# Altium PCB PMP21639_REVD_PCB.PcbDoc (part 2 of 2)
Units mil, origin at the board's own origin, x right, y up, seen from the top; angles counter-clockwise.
Board outline 3667.52 x 1155.04 mil, 4 copper layers (Top Layer, Signal Layer 1, Signal Layer 2, Bottom Layer), stack 90.224 mil thick; 122 components, 73 nets, 372 pads, 102 vias.
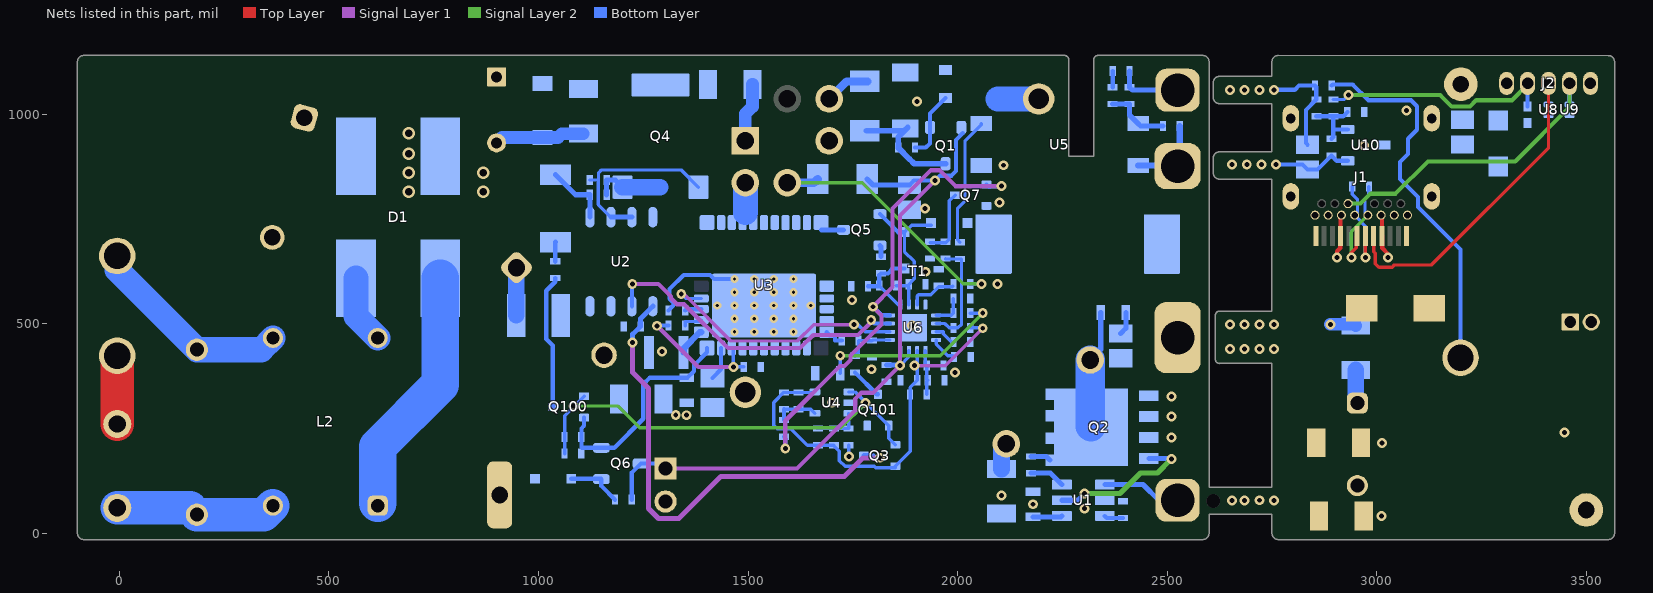
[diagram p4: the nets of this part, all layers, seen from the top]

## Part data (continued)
U10: library part CMP-0066199-1, "2.5V Low Iq Adjustable Precision Shunt Regulator, DBZ0003A (SOT-23-3)", Alternate Manufacturer="Texas Instruments"

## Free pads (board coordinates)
  rrect50% 105.31x102.36 hole 80: 0(2525,1057.09) 2(2525,78.74)
  rrect50% 110x110 hole 80: 1(2525,875.98)
  round 33 hole 33 unplated: 1(2610,76.69)
  rrect50% 60x160 hole 40 slot 120 at 90 deg: 2(907.38,91.54)
  rrect50% 110x170 hole 80 slot 140 at 90 deg: 2(2525,466.76)

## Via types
v1: diameter 23.62, hole 11.81, Top Layer to Bottom Layer, 72 vias
v2: diameter 19.68, hole 7.87, Top Layer to Bottom Layer, 22 vias
v3: diameter 30, hole 18, Top Layer to Bottom Layer, 6 vias
v4: diameter 23.62, hole 11.81, Top Layer to Bottom Layer, tented bottom, 2 vias

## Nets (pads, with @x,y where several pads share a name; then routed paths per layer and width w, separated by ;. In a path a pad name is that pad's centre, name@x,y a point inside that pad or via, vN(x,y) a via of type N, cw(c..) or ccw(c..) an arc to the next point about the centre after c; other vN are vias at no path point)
CC1: J1.A5 J2.3 U8.1 | length 806.9
  Top Layer w8: J1.A5@2992.64,709.29 2992.64,671.9 2996.64,667.9 2996.64,643.36 3005.33,634.67 3036.9,634.67 3042.23,640 3129.9,640 3410,920.1 J2.3@3410,1073.49
  Bottom Layer w8: U8.1@3410,1022.8 J2.3@3410,1073.49
CC2: J1.B5 J2.4 U9.1 | length 731
  Signal Layer 2 w10: J1.B5@2931.61,786.46 2961.09,786.46 2984.79,810.16 3045.16,810.16 3122.2,887.2 3330.46,887.2 3460,1016.75 J2.4@3460,1073.49
  Bottom Layer w12: U9.1@3460,1023.06 J2.4@3460,1073.49
CTL: J2.2 R42.1 R43.2 | length 559
  Signal Layer 2 w10: v1(2932.41,1045.91) 3151.39,1045.91 3178.85,1018.44 3222.66,1018.44 3237.27,1033.06 3322.67,1033.06 3360,1070.39 J2.2@3360,1073.49
  Bottom Layer w8: R42.1@2896.6,1034.79 2921.3,1034.79 v1(2932.41,1045.91)
  Bottom Layer w10: R43.2@3360,1018.53 J2.2@3360,1073.49
DN: J1.A7 J1.B7 R39.2 | length 248.4
  Top Layer w8: v1(2939.49,658.36) 2939.49,668.88 2951.36,680.75 2951.36,707.39 J1.A7@2953.27,709.29
  Signal Layer 2 w8: v1(2939.49,658.36) 2939.49,718.92 2978.86,758.29 J1.B7@2978.86,758.9
  Bottom Layer w8: J1.B7@2978.86,758.9 2971.91,765.85 2971.91,797.46 2981.36,806.91 R39.2@2981.36,827
DP: J1.A6 J1.B6 R39.1 | length 239
  Top Layer w8: v1(2972.95,658.09) J1.A6@2972.95,709.29
  Bottom Layer w8: R39.1@2941.36,827 2941.36,808.95 2954.31,796 2954.31,765.85 J1.B6@2947.36,758.9 2947.36,758.29 2972.95,732.7 v1(2972.95,658.09)
FB: C25.1 R21.1 R25.2 U6.10 | length 262.7
  Bottom Layer w8: U6.10@1948.78,500.32 1969.94,500.32 1980.25,490 C25.1@1990,490 2000.49,490 2009.37,498.89 2009.37,654.42 R21.1@2005.59,654.42 1972.04,654.42 R25.2@1971.14,655.32
HVG: C31.1 D7.2 D100.2 Q5.1 R11.2 U6.6 | length 365.3
  Bottom Layer w8: R11.2@1853.19,590.59 C31.1@1880.59,590.59 ; U6.6@1883.82,545.59 1883.82,587.36 C31.1@1880.59,590.59 ; D100.2@1937.01,735.16 1890.08,735.16 D7.2@1873.23,718.31 1873.23,672.11 1896.91,648.42 1896.91,606.91 C31.1@1880.59,590.59
  Bottom Layer w10: Q5.1@1814.53,761.33 1857.55,718.31 D7.2@1873.23,718.31
NetC1_1: C1.1 D1.1 L1.1
NetC2_1: C2.1 C3.1 C6.1 C7.1 D3.2 L1.2 T1.1 | length 472.2
  Bottom Layer w30: L1.2@900,931.26 912.9,944.16 D3.2@1010,944.16 1046.53,944.16 1055.87,953.51 C6.1@1107.24,953.51 ; T1.1@1493.59,936.3 1493.59,1001.03 1510.59,1018.03 C7.1@1510.59,1071.13
  Bottom Layer w40: C3.1@946.85,520 946.85,632.18 C2.1@948.02,633.35
NetC5_1: C5.1 R1.1 | length 54.9
  Bottom Layer w12: R1.1@2389.17,476.69 2401.54,489.06 C5.1@2401.54,526.5
NetC5_2: C5.2 Q2.5 Q2.6 Q2.7 Q2.8 Q2.9 R3.2 T1.7 | length 332.9
  Bottom Layer w12: R3.2@2175,183.19 2211.42,183.19 Q2.5@2220,174.6 ; T1.7@2316.42,413.47 2341.54,438.58 C5.2@2341.54,526.5
  Bottom Layer w70: T1.7@2316.42,413.47 2316.42,255.35 Q2.9@2318.43,253.34
NetC6_2: C6.2 C7.2 D3.1 Q4.2
NetC9_2: C9.2 D2.1 Q1.3 R2.1 | length 277.5
  Bottom Layer w13.78: D2.1@1782.69,960.16 C9.2@1872.88,960.16 ; C9.2@1881.08,968.36 C9.2@1872.88,960.16 ; Q1.3@1971.61,881.75 1896.47,881.75 1884.97,893.24 1884.6,893.24 1858.21,919.62 R2.1@1858.21,920 1858.21,945.49 C9.2@1872.88,960.16
NetC10_1: C10.1 L2.4 NEUT.1 | length 495.6
  Bottom Layer w60: NEUT.1@-5,661.66 -5,627.86 C10.1@185,437.86 338.53,437.86 L2.4@366.5,465.83
NetC10_2: C10.2 F1.1 L2.2 | length 387.2
  Bottom Layer w80: F1.1@-5,60.5 168.66,60.5 C10.2@185,44.16 344.83,44.16 L2.2@366.5,65.83
NetC11_1: C11.1 U1.4 | length 69.7
  Bottom Layer w12: C11.1@2180,39.2 2246.68,39.2 U1.4@2248.82,41.34
NetC13_1: C13.1 D6.1 U2.5 | length 155.3
  Bottom Layer w12: D6.1@1040.62,855.32 1088.34,807.6 C13.1@1122.68,807.6 1122.84,807.44 U2.5@1122.84,754.17
NetC15_1: C15.1 Q3.3 U2.1 | length 1180.1
  Signal Layer 1 w12: v1(1224.8,455) 1224.8,383.71 1262.7,345.81 1262.7,58.88 1286.4,35.18 1334.8,35.18 1435.12,135.5 1729.85,135.5 1774.36,180 v1(1814.53,180)
  Bottom Layer w12: v1(1224.8,455) 1224.8,474.79 C15.1@1243.8,493.78 1243.8,512.53 U2.1@1272.84,541.57 ; Q3.3@1776.63,185.44 1797.4,185.44 1802.84,180 v1(1814.53,180)
NetC16_2: C16.2 C17.1 C20.2 L3.1 R15.1 R22.2 R23.2 U3.12 U3.13 U3.14 U3.15 U3.16 U3.18 U3.19 U3.20 U3.21 U3.22 U3.23 U3.24 U3.33@1538.19,543.39 | length 284.8
  Bottom Layer w10: R15.1@1310,531.57 1322.5,544.07 1322.5,549.74 1312.77,559.47 1312.77,582.57 1346.51,616.31 1409.29,616.31 U3.33@1419.17,606.42 ; U3.33@1419.17,606.38 v2(1467.91,606.38) ; U3.16@1687.8,479.42 1694.61,472.6 1707.21,472.6 1707.21,460 R23.2@1723.66,460
  other v1: 1327.5,282.01 1352.97,281.61 1295,434.02
  other v2: 1467.91,480.4 1514.76,480.4 1561.61,480.4 1608.46,480.4 1467.91,511.9 1514.76,511.9 1561.61,511.9 1608.46,511.9 1426.57,543.39 1467.91,543.39 1514.76,543.39 1561.61,543.39 1608.46,543.39 1649.8,543.39 1467.91,574.89 1514.76,574.89 1561.61,574.89 1608.46,574.89 1514.76,606.38 1561.61,606.38 1608.46,606.38
NetC17_2: C17.2 R10.2 U3.25 | length 320.9
  Signal Layer 1 w10: v1(1283.15,495) 1381.15,397 v1(1465,397)
  Bottom Layer w8: U3.25@1461.42,442.01 1465,438.43 v1(1465,397) C17.2@1490,397
  Bottom Layer w10: v1(1283.15,495) 1283.5,495.35 R10.2@1310,495.35
NetC18_2: C18.2 R13.1 R17.1 U4.4 | length 104.1
  Bottom Layer w8: R13.1@1585.55,295.82 C18.2@1620,295.82 1649.65,295.82 U4.4@1659.65,285.82
  Bottom Layer w10: R17.1@1585.55,270 R13.1@1585.55,295.82
NetC20_1: C20.1 U3.26 | length 80.2
  Bottom Layer w10: C20.1@1415,370.43 1435.83,391.26 U3.26@1435.83,442.01
NetC21_1: C21.1 R16.2 | length 39
  Bottom Layer w10: C21.1@2370,1064.1 R16.2@2370,1103.1
NetC21_2: C21.2 R19.1 R24.2 U5.1 | length 157.1
  Bottom Layer w12: C21.2@2370,1024.1 2370.05,1024.04 R19.1@2410,1024.04 2410,998.03 U5.1@2430.54,977.49 2436.66,971.37 R24.2@2490,971.37
NetC24_2: C24.2 R18.1 R23.1 U6.1 | length 115.5
  Bottom Layer w8: R18.1@1755,423.61 1763.66,432.27 R23.1@1763.66,460 1763.98,459.68 C24.2@1795.86,459.68 1797.12,460.94 U6.1@1838.54,460.94
NetC26_1: C26.1 Q7.3 R25.1 | length 160.9
  Bottom Layer w8: C26.1@1934.21,693.81 1935.21,692.82 1971.46,692.82 1980.32,701.67 1980.32,792.93 Q7.3@1994.05,806.67
NetC29_1: C29.1 R32.2 R36.2 U6.13 | length 107.1
  Bottom Layer w8: U6.13@1923.19,435.35 1923.19,403.03 C29.1@1926.22,400 1926.22,367.4 R36.2@1928.62,365 1926.65,363.03 R32.2@1926.65,331.31
NetC38_1: C38.1 R41.1 R42.2 R45.1 U10.2 | length 169.8
  Bottom Layer w10: R41.1@2855.83,995 2896.39,995 R42.2@2896.6,994.79 ; C38.1@2891.99,941.12 2896.18,945.31 2896.18,960.98 ; R45.1@2930,1004.75 2920.04,994.79 R42.2@2896.6,994.79 ; U10.2@2930.92,963.48 2898.68,963.48 2896.18,960.98 ; 2896.18,960.98 2896.18,994.37 R42.2@2896.6,994.79
NetC100_2: C100.2 Q3.1 Q100.1 Q101.1 R100.1 U4.1 | length 1080.1
  Signal Layer 2 w8: v1(1083.15,303.49) 1189.77,303.49 1241.61,251.65 1721.56,251.65 v1(1780.29,310.38)
  Bottom Layer w8: R100.1@1062.31,190 C100.2@1062.31,230.01 1062.31,280.47 Q100.1@1108.93,327.08 ; U4.1@1740.35,337.01 1755.37,337.01 Q101.1@1835.59,256.78 1835.59,226.88 Q3.1@1851.44,211.03
NetC101_2: C101.2 R14.1 R20.2 U4.3 | length 109.3
  Bottom Layer w8: R14.1@1666.67,250 C101.2@1705,250 R20.2@1740,250 1740,285.47 U4.3@1740.35,285.82
NetC200_2: C200.2 R200.2 U6.9 | length 78.3
  Bottom Layer w8: U6.9@1948.78,520 1985,520 R200.2@1990,525 C200.2@1990,560
NetD1_2: D1.2 L2.3 | length 164.2
  Bottom Layer w60: D1.2@564.61,608.5 564.61,517.72 L2.3@616.5,465.83
NetD1_3: D1.3 L2.1 | length 598
  Bottom Layer w90: L2.1@616.5,72.13 616.5,206.22 765.39,355.12 D1.3@765.39,608.5
NetD2_2: D2.2 T1.9 | length 108.7
  Bottom Layer w19.68: T1.9@1693.59,1036.3 1735.39,1078.11 D2.2@1785,1078.11
NetD4_1: D4.1 Q1.1 R2.2 | length 163.9
  Bottom Layer w10: R2.2@1898.21,920 1924.06,920 1934.2,930.14 Q1.1@1934.2,968.36 1934.2,1001.57 D4.1@1971.14,1038.5
NetD6_2: D6.2 R4.2 | length 46.2
  Bottom Layer w11.81: R4.2@1040,648.79 1040,694.06 D6.2@1040.62,694.68
NetD8_1: D8.1 Q6.1 R9.1 | length 134.7
  Bottom Layer w10: D8.1@1078.31,130 1149.02,130 Q6.1@1150,129.02 1150,112.76 R9.1@1182.76,80
NetF1_2: F1.2 LINE.1 | length 163.1
  Top Layer w80: F1.2@-5,260.5 LINE.1@-5,423.61
NetL3_2: L3.2 U3.28 | length 67.9
  Bottom Layer w15: L3.2@1346.34,431.22 1346.34,440.88 1384.87,479.42 U3.28@1388.58,479.42
NetQ2_4: Q2.4 U1.5 | length 356.2
  Signal Layer 2 w12: v1(2302.76,94.95) 2387.74,94.95 2436.59,143.8 2476.86,143.8 v1(2510,176.93)
  Bottom Layer w12: U1.5@2248.82,78.74 2286.55,78.74 v1(2302.76,94.95) ; Q2.4@2456.22,178.34 2508.59,178.34 v1(2510,176.93)
NetQ4_1: Q4.1 R8.2 U2.6 U2.7 | length 446.7
  Bottom Layer w8: R8.2@1122.68,842.81 1142.68,842.81 ; U2.6@1172.84,754.17 1142.68,784.33 1142.68,836.5 1143.3,837.12 1143.3,859.73 1150.26,866.68 1340.64,866.68 Q4.1@1381.77,825.56
  Bottom Layer w12: U2.6@1172.84,754.17 U2.7@1222.84,754.17
NetQ5_2: Q5.2 R12.2 | length 27.5
  Bottom Layer w12: Q5.2@1814.53,686.53 1816.89,684.17 R12.2@1816.89,660
NetQ100_3: Q100.3 R4.1 | length 322.6
  Bottom Layer w10: Q100.3@1034.13,301.49 1034.13,447.98 1018.62,463.49 1018.62,578.62 1040,600 R4.1@1040,608.79
NetQ101_3: Q101.3 R18.2 | length 76.5
  Bottom Layer w10: R18.2@1755,383.61 1807.02,331.59 Q101.3@1810,331.59
NetR3_1: R3.1 U1.6 | length 85
  Bottom Layer w12: R3.1@2175,143.19 2221.77,143.19 U1.6@2248.82,116.14
NetR6_1: R6.1 U1.3 | length 45.6
  Bottom Layer w10: U1.3@2351.18,41.34 2355.9,36.62 R6.1@2394.8,36.62
NetR10_1: R10.1 U3.29 | length 49.9
  Bottom Layer w8: R10.1@1350,495.35 1350,505.07 1384.71,505.07 U3.29@1388.58,508.94
NetR15_2: R15.2 U3.30 | length 39.8
  Bottom Layer w10: R15.2@1350,531.57 1352.97,534.53 U3.30@1388.58,534.53
NetR21_2: R21.2 U5.4 | length 308.9
  Bottom Layer w8: R21.2@2005.59,694.42 1999.94,700.07 1999.94,775.84 2017.74,793.64 2017.74,936.2 2056.53,974.99 U5.4@2056.53,977.49
NetR26_2: R26.2 U6.11 | length 54.5
  Bottom Layer w8: U6.11@1948.78,480.63 1965.65,480.63 1965.65,476.24 1986.06,455.83 R26.2@1990.44,455.83
NetR28_1: R28.1 U6.12 | length 64.8
  Bottom Layer w8: U6.12@1948.78,460.94 1948.78,451.47 1976.38,423.87 1988.39,423.87 R28.1@1991.45,420.81
NetR37_2: R37.2 R38.2 U6.7 | length 115.3
  Bottom Layer w8: U6.7@1903.5,545.59 1903.5,566.19 1906.59,569.28 1936.01,569.28 1955,588.27 1987.65,588.27 R37.2@1988.64,589.25
NetR200_1: R200.1 RT1.2 | length 454
  Signal Layer 2 w8: v1(1720,423.61) 1720.08,423.68 1958.4,423.68 v1(2060,525.28)
  Bottom Layer w8: RT1.2@1720,381.85 v1(1720,423.61) ; R200.1@2030,525 2059.72,525 v1(2060,525.28)
OPTO_BOTTOM: C38.2 R101.2 U10.1 | length 194.7
  Bottom Layer w10: v1(2760,879.83) 2823.2,879.83 R101.2@2835,868.03 2858.9,868.03 C38.2@2891.99,901.12 2904.43,888.68 U10.1@2930.92,888.68
  other v1: 2655,879.52 2690,879.52 2725,879.52
OPTO_BOTTOM1: pad.1@2525,875.98 R24.1 U5.2 | length 192.5
  Bottom Layer w15: U5.2@2430.54,877.49 2523.49,877.49 pad.1@2525,875.98 2530,880.98 R24.1@2530,971.37
OPTO_TOP: R40.1 R41.2 R101.1 | length 256.2
  Bottom Layer w10: v1(2755,1057.93) 2804.54,1057.93 2814.77,1068.17 R40.1@2852.61,1068.17 2855.83,1064.95 R41.2@2855.83,1035 2830.95,1010.13 2830.95,931.13 R101.1@2835,927.08
  other v1: 2650,1057.62 2685,1057.62 2720,1057.62
OPTO_TOP1: pad.0 R16.1 R19.2 | length 156.9
  Bottom Layer w12: R16.1@2410,1103.1 R19.2@2410,1064.04 2416.95,1057.09 pad.0@2525,1057.09
PGND: C1.2 C2.2 C3.2 C9.1 C12.2 C14.1 C15.2 C19.2 C23.2 C24.1 C26.2 C27.2 C29.2 C30.2 C31.2 C200.1 D1.4 D4.2 D8.2 D100.1 pad.2@907.38,91.54 Q7.2 Q101.2 R20.1 R22.1 R26.1 R28.2 R36.1 R38.1 RT1.1 T1.8 T1.11 T1.12 U2.3 U2.4 U4.2 U5.3 U6.8 U6.16 U6.17@1893.66,490.47 | length 129.4
  Bottom Layer w8: R20.1@1740,210 1740,184.41 v1(1741.22,183.19)
  Bottom Layer w60: 2096.27,1036.3 T1.11@2193.59,1036.3 T1.11@2196.96,1032.93
  other v1: 1700,311.42 1993.56,383.61 1891.25,495.3 2095,595 1923.19,623.9 1922.56,775 2100,788.69 2109.42,878.06 1903.5,1030
  other v3: 690,815 868.15,815 690,860 868.2,859.73 690,905.4 690,954.44
  other v4: 1795,391.26 1748.46,556.09
PWMH: U2.2 U6.3 | length 768
  Signal Layer 1 w10: v1(1223.82,595) 1285.95,595 1315.96,564.99 1315.96,560.8 1330.42,546.33 1347.4,546.33 1451.93,441.81 1624.45,441.81 1655.55,472.91 1762.78,472.91 1793.9,504.03 v1(1793.9,508.39)
  Bottom Layer w10: U2.2@1222.84,541.57 1222.84,594.02 v1(1223.82,595) ; v1(1793.9,508.39) 1801.97,500.32 U6.3@1838.54,500.32
PWML: U3.31 U6.2 | length 620
  Signal Layer 1 w8: v1(1340.64,571.02) 1346.58,571.02 1458.92,458.68 1617.46,458.68 1656.38,497.6 v1(1752.56,497.6)
  Bottom Layer w8: v1(1340.64,571.02) 1351.54,560.12 U3.31@1388.58,560.12 ; v1(1752.56,497.6) 1762.35,497.6 1779.32,480.63 U6.2@1838.54,480.63
REF: C18.1 C25.2 C27.1 C101.1 Q3.2 R13.2 R14.2 R32.1 U4.5 U6.14 | length 1044
  Signal Layer 1 w8: v1(1897.6,400) 1970.94,400 v1(2060,489.06)
  Bottom Layer w8: U4.5@1659.65,337.01 1658.46,335.82 R13.2@1585.55,335.82 1561.68,311.95 1561.68,257.58 1569.88,249.37 1602.47,249.37 1641.84,210 R14.2@1666.67,210 C101.1@1705,210 1705,208.71 1717.54,196.17 1717.54,173.38 1731.41,159.5 1801.53,159.5 1804.72,156.32 1851.44,156.32 Q3.2@1851.44,159.85 1886.65,195.07 R32.1@1886.65,331.31 1886.65,347.83 C27.1@1903.82,365 1903.82,393.78 v1(1897.6,400) 1903.5,405.91 U6.14@1903.5,435.35 ; C25.2@2030,490 2059.06,490 v1(2060,489.06)
RUN: Q7.1 R17.2 U6.4 | length 1132.2
  Signal Layer 1 w10: v1(1588.87,202.05) 1588.87,268.46 1719.34,398.92 1730.22,398.92 1744.68,413.38 1744.68,424.27 1818.58,498.17 1818.58,519.91 v1(1798.06,540.44) 1844.84,587.23 1844.84,774.86 1936.28,866.3 1956.73,866.3 1994.92,828.11 v1(2105,828.11)
  Bottom Layer w10: R17.2@1585.55,230 1588.87,226.68 v1(1588.87,202.05) ; v1(1798.06,540.44) 1818.5,520 U6.4@1838.54,520 ; Q7.1@2068.85,832.26 2073,828.11 v1(2105,828.11)
S: C33.1 C34.1 L4.1 L5.1 | length 61.5
  Bottom Layer w30: v1(2889.75,498.46) 2947.09,498.46 L4.1@2950,495.55
  other v1: 2655,77.76 2685,77.76 2755,77.76 2720,78.74
S1: C8.1 pad.2@2525,78.74 T1.4 U1.1 | length 209
  Bottom Layer w12: U1.1@2351.18,116.14 2442.6,116.14 pad.2@2480,78.74
  Bottom Layer w40: C8.1@2105,153.54 2105,202.05 T1.4@2116.42,213.47
SGND: C32.2 C33.2 C34.2 C36.2 D9.2 J1.A1 J1.A12 J1.B1 J1.B12 J1.M1 J1.M2 J1.S1 J1.S2 J1.S3 J1.S4 J2.5 J3.2 R43.1 R45.2 TP3.1 U8.2 U9.2 U10.3
  other v1: 3011.76,41.34 3012.32,215.57 3448.15,240 2650,440 2685,440 2720,440 2755,440 2650,498.46 2685,498.46 2720,498.46 2755,498.46 2969.27,925 3071.43,1008.46
SGND1: C8.2 C11.2 C19.1 pad.2@2525,466.76 Q2.1 Q2.2 Q2.3 R1.2 R6.2 U1.2
  other v1: 2302.76,58.51 2180,69.2 2105,90 2510,228.42 2510,278.93 2510,326.61
SWS: C30.1 D7.1 R11.1 R12.1 U6.5 | length 189.1
  Bottom Layer w8: R11.1@1813.19,590.59 1858.19,545.59 U6.5@1864.13,545.59
  Bottom Layer w10: C30.1@1786.34,589.25 1811.85,589.25 R11.1@1813.19,590.59 1813.19,616.3 R12.1@1816.89,620 1833.64,620 1845.33,631.69 D7.1@1873.23,631.69
VBUS: C36.1 D9.1 J1.A4 J1.A9 J1.B4 J1.B9 J2.1 TP1.1 | length 212.6
  Top Layer w10: v1(2905.47,658.09) 2905.47,672.82 2912.99,680.34 2912.99,708.39 J1.A9@2913.9,709.29 2913.9,756.93 J1.B4@2915.87,758.9 ; J1.B9@3010.35,758.9 3012.32,756.93 J1.A4@3012.32,709.29 3013.23,708.39 3013.23,680.34 3027.09,666.48 v1(3027.09,658.36)
VCCL: C16.1 C100.1 Q6.2 Q100.2 R100.2 U3.27 | length 535.2
  Bottom Layer w10: Q100.2@1108.93,275.9 1108.93,256.62 1102.31,250 C100.1@1102.31,230.01 1102.31,205 1103.49,203.83 Q6.2@1150,203.83 1180.68,203.83 1250,273.15 1250,355.43 1265.72,371.16 C16.1@1353.5,371.16 1355.66,371.16 1371.02,386.52 1371.02,400.48 1402.36,431.82 U3.27@1402.36,442.01
VDD: C12.1 C14.2 C23.1 D5.1 Q1.2 Q6.3 R9.2 U6.15 | length 1718.7
  Signal Layer 1 w10: C12.1@1303.15,154.37 1617.09,154.37 1755.6,292.88 1755.6,320.6 1770.06,335.06 1797.78,335.06 v1(1862.72,400) 1862.72,757.82 v1(1946.51,841.61)
  Bottom Layer w8: v1(1862.72,400) 1883.82,421.1 U6.15@1883.82,435.35
  Bottom Layer w10: R9.2@1222.76,80 1222.76,144.69 Q6.3@1244.49,166.42 1291.1,166.42 C12.1@1303.15,154.37 ; C14.2@1885,831 1895.61,841.61 v1(1946.51,841.61) 1958.02,853.12 1985.29,853.12 1996.29,864.12 1996.29,938.62 Q1.2@2012.1,954.42
  Bottom Layer w12: D5.1@1784.06,845 1798.06,831 C14.2@1885,831 ; C23.1@1830.29,401.46 1861.25,401.46 v1(1862.72,400)
VO: C32.1 J3.1 L4.2 L5.2 R40.2 TP2.1 | length 982.9
  Bottom Layer w10: R40.2@2892.61,1068.17 2895.03,1070.59 2942.64,1070.59 2980.08,1033.15 3081.66,1033.15 3096.12,1018.69 3096.12,962.77 3074.68,941.34 3074.68,905.18 3055.6,886.09 3055.6,845.53 3098.66,802.47 3098.66,778.48 3200,677.14 TP2.1@3200,418.74
  Bottom Layer w40: L4.2@2950,389.25 2950,314.23 C32.1@2953.76,310.47
VS: D5.2 R37.1 T1.3 | length 667.3
  Signal Layer 2 w8: T1.3@1593.59,836.3 1772.6,836.3 2013.9,595 v1(2057.5,595)
  Bottom Layer w8: R37.1@2030,595 v1(2057.5,595)
  Bottom Layer w20: T1.3@1593.59,836.3 1657.25,836.3 D5.2@1665.94,845
VSW: C13.2 Q4.3 Q5.3 R8.1 T1.2 U2.8 U3.1 U3.2 U3.3 U3.4 U3.5 U3.6 U3.7 U3.8 U3.9 U3.10 U3.11 | length 293.9
  Bottom Layer w12: C13.2@1162.68,807.6 R8.1@1162.68,842.81 1183.41,842.81 Q4.3@1200.67,825.56 ; U3.11@1675.24,723.93 Q5.3@1727.91,723.93
  Bottom Layer w40: Q4.3@1200.67,825.56 1290.47,825.56
  Bottom Layer w60: 1493.59,765.19 T1.2@1493.59,836.3
pads on no net: J1.A2 J1.A3 J1.A8 J1.A10 J1.A11 J1.B2 J1.B3 J1.B8 J1.B10 J1.B11 T1.10 U3.17 U3.32 U3.33@1444.49,508.39 U3.33@1444.49,579.26 U3.33@1491.34,508.39 U3.33@1491.34,579.26 U3.33@1538.19,508.39 U3.33@1538.19,579.26 U3.33@1585.04,508.39 U3.33@1585.04,579.26 U3.33@1631.89,508.39 U3.33@1631.89,579.26 U6.17@1893.66,490.47 U8.1S U8.2S U9.1S U9.2S

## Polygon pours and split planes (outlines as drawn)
PGND on Signal Layer 1 "SIGNAL_LAYER_1_PGND_P366" (solid, remove dead copper, pour order 366): 795,1125 795,7.55 2131.48,7.55 2131.48,1125
PGND on Signal Layer 1 "SIGNAL_LAYER_1_PGND_P365" (solid, remove dead copper, pour order 365): 265,1130 265,649.05 2131.48,649.05 2131.48,1130
VBUS on Signal Layer 1 "SIGNAL_LAYER_1_VBUS_P369" (solid, remove dead copper, pour order 369): 2765,1123.81 2765,615 3332.21,615 3332.21,1124.73
SGND on Signal Layer 1 "SIGNAL_LAYER_1_SGND_P370" (solid, remove dead copper, pour order 370): 2640,1137.52 2640,0 3565,0 3565,1137.52
SGND1 on Signal Layer 1 "SIGNAL_LAYER_1_SGND1_P367" (solid, remove dead copper, pour order 367): 2350,774.86 2350,0 2600,0 2600,774.86
SGND1 on Signal Layer 1 "SIGNAL_LAYER_1_SGND1_P368" (solid, remove dead copper, pour order 368): 2550,-10.02 2085.55,-10.02 2085.55,229.1 2395.23,538.77 2542.14,538.77
PGND on Signal Layer 2 "SIGNAL_LAYER_2_PGND_P373" (solid, remove dead copper, pour order 373): 795,735.74 795,5.87 2131.48,5.87 2131.48,735.74
PGND on Signal Layer 2 "SIGNAL_LAYER_2_PGND_P372" (solid, remove dead copper, pour order 372): 265,1130 265,649.05 2131.48,649.05 2131.48,1130
NetC16_2 on Signal Layer 2 "SIGNAL_LAYER_2_NETC16_2_P371" (solid, remove dead copper, pour order 371): 1251.85,624.89 1251.85,268.41 1717.48,268.41 1717.48,624.89
SGND on Signal Layer 2 "SIGNAL_LAYER_2_SGND_P380" (solid, remove dead copper, pour order 380): 2625,1125 2625,860.09 2625,0 3565,0 3565,1125
no net on Signal Layer 2 "SIGNAL_LAYER_2_NONET_P378" (solid, remove dead copper, pour order 378): 496.38,762.64
SGND1 on Signal Layer 2 "SIGNAL_LAYER_2_SGND1_P374" (solid, remove dead copper, pour order 374): 2350,786.46 2350,0 2600,0 2600,786.46
SGND1 on Signal Layer 2 "SIGNAL_LAYER_2_SGND1_P376" (solid, remove dead copper, pour order 376): 2565.91,-10.02 2084.97,-10.02 2085.85,230.11 2359.77,504.03 2558.54,504.03
S on Bottom Layer "BOTTOM_LAYER_S_P362" (solid, remove dead copper, pour order 362): 2640.14,109.82 2640.14,44.82 2788.65,44.55 2788.65,109.82
VBUS on Bottom Layer "BOTTOM_LAYER_VBUS_P360" (solid, remove dead copper, pour order 360): 3165.09,1135 3165.09,961.26 3325,960.96 3325,1135
OPTO_BOTTOM on Bottom Layer "BOTTOM_LAYER_OPTO_BOTTOM_P359" (solid, remove dead copper, pour order 359): 2626.29,910 2626.29,845 2774.81,844.73 2774.8,910
SGND1 on Bottom Layer "BOTTOM_LAYER_SGND1_P357" (solid, remove dead copper, pour order 357): 2070,178.34 2070,-10.13 2452.93,-10.13 2452.93,178.34
SGND1 on Bottom Layer "BOTTOM_LAYER_SGND1_P356" (solid, remove dead copper, pour order 356): 2350,810.16 2350,-10.02 2600,-10.02 2600,810.16
S1 on Bottom Layer "BOTTOM_LAYER_S1_P355" (solid, remove dead copper, pour order 355): 2414.68,155 2414.68,-2.22 2600,-2.22 2600,155
PGND on Bottom Layer "BOTTOM_LAYER_PGND_P354" (solid, remove dead copper, pour order 354): 874.27,1125 874.27,0 2127.5,0 2127.5,1125
PGND on Bottom Layer "BOTTOM_LAYER_PGND_P353" (solid, remove dead copper, pour order 353): 650,1125 650,647.87 2131.48,647.87 2131.48,1125
NetC16_2 on Bottom Layer "BOTTOM_LAYER_NETC16_2_P352" (solid, remove dead copper, pour order 352): 1240,381.73 1240,268.41 1443.52,268.41 1443.52,381.73
NetC16_2 on Bottom Layer "BOTTOM_LAYER_NETC16_2_P351" (solid, remove dead copper, pour order 351): 1251.85,624.89 1251.85,368.31 1715.63,368.31 1715.63,624.89
VSW on Bottom Layer "BOTTOM_LAYER_VSW_P350" (solid, remove dead copper, pour order 350): 1260,857.56 1260,703.05 1520,703.05 1520,857.56
VSW on Bottom Layer "BOTTOM_LAYER_VSW_P349" (solid, remove dead copper, pour order 349): 1372.87,768.13 1372.87,703.05 1695.21,703.05 1695.21,768.13
NetC1_1 on Bottom Layer "BOTTOM_LAYER_NETC1_1_P348" (solid, remove dead copper, pour order 348): 380.5,1120 380.5,936.3 945.51,936.3 945.51,1120
NetC6_2 on Bottom Layer "BOTTOM_LAYER_NETC6_2_P347" (solid, remove dead copper, pour order 347): 965,1118.27 965,1026.34 1430.63,1026.34 1430.63,1118.27
SGND on Bottom Layer "BOTTOM_LAYER_SGND_P364" (solid, remove dead copper, pour order 364): 2625,1125 2625,860.77 2625,0 3565,0 3565,1125
OPTO_TOP on Bottom Layer "BOTTOM_LAYER_OPTO_TOP_P358" (solid, remove dead copper, pour order 358): 2625,1090 2625,1025 2773.52,1024.73 2773.51,1090
OPTO_BOTTOM on Top Layer "TOP_LAYER_OPTO_BOTTOM_P343" (solid, remove dead copper, pour order 343): 2625,910.22 2625,845.22 2773.96,845.22 2773.96,910.22
SGND1 on Top Layer "TOP_LAYER_SGND1_P339" (solid, remove dead copper, pour order 339): 2083.51,510.01 2083.51,252.17 2560.02,252.17 2560.02,510.01
S1 on Top Layer "TOP_LAYER_S1_P337" (solid, remove dead copper, pour order 337): 2083.51,247.82 2083.51,-10.02 2600.02,-10.02 2600.02,247.82
PGND on Top Layer "TOP_LAYER_PGND_P336" (solid, remove dead copper, pour order 336): 795,699.58 795,0 2131.48,0 2131.48,699.58
PGND on Top Layer "TOP_LAYER_PGND_P335" (solid, remove dead copper, pour order 335): 265,1125 265,647.87 2130.98,647.87 2130.98,1125
NetC2_1 on Top Layer "TOP_LAYER_NETC2_1_P334" (solid, remove dead copper, pour order 334): 873.24,973.58 873.24,593.19 1532.34,593.19 1532.34,973.58
SGND on Top Layer "TOP_LAYER_SGND_P346" (solid, remove dead copper, pour order 346): 2625,1125 2625,-12.52 3565,-12.52 3565,1125
OPTO_TOP on Top Layer "TOP_LAYER_OPTO_TOP_P345" (solid, remove dead copper, pour order 345): 2625,1090 2625,1025 2770,1025 2770,1090
no net on Top Layer "TOP_LAYER_NONET_P344" (solid, remove dead copper, pour order 344): 3200,747.32
S on Top Layer "TOP_LAYER_S_P340" (solid, remove dead copper, pour order 340): 2640,394.36 2640,-12.52 2908.98,-12.52 2908.98,394.36
VO on Top Layer "TOP_LAYER_VO_P342" (solid, remove dead copper, pour order 342): 2903.78,574.19 2903.78,275.16 3482.21,275.16 3482.21,574.19
S on Top Layer "TOP_LAYER_S_P341" (solid, remove dead copper, pour order 341): 2761.98,574.19 2761.98,375 3007.86,375 3007.86,574.19
SGND1 on Top Layer "TOP_LAYER_SGND1_P338" (solid, remove dead copper, pour order 338): 2350,810.48 2350,257.56 2600,257.56 2600,810.48

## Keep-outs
Keep-Out Layer:
  text ".Layer_Name" at 406,-1642.93 h23.62

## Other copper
Top Layer:
  pour cut-out: 1919.9,248.19 1920.43,248.72 1920.43,290.45 2150.99,521.01 2351.18,521.01 2351.18,497.64 2101.33,247.78
  pour cut-out: 1919.91,247.49 2082.88,247.49 2082.88,-11.19 1920.9,-11.19
  pour cut-out: 1229.11,1120
  pour cut-out: 1195,813.07
  text ".Layer_Name" at 406,-1642.93 h23.62
Signal Layer 1:
  pour cut-out: 1030,869.53 1689.83,869.53 1689.83,703.63 1030.64,703.63
  pour cut-out: 1919.9,248.19 1920.43,248.72 1920.43,290.45 2150.99,521.01 2265,521.01 2265,429.31 2083.51,247.82
  pour cut-out: 1919.9,248.19 2082.88,248.19 2082.88,-11.19 1920.9,-11.19
Signal Layer 2:
  pour cut-out: 1035.38,869.53 1695.21,869.53 1695.21,703.63 1036.02,703.63
  pour cut-out: 1919.9,248.19 1920.43,248.72 1920.43,290.45 2150.99,521.01 2265,521.01 2265,429.31 2083.51,247.82
  pour cut-out: 1919.9,248.19 2082.88,248.19 2082.88,-11.19 1920.9,-11.19
Bottom Layer:
  pour cut-out: 1919.26,248.19 1919.79,248.72 1919.79,290.45 2150.35,521.01 2264.36,521.01 2264.36,429.31 2082.87,247.82
  pour cut-out: 1904.46,217.77 2067.31,217.77 2067.31,-9.67 1905.33,-9.67
  text ".Layer_Name" at 406,-1642.93 h23.62

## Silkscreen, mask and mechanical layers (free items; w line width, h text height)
Top Overlay:
  text "T1" at 2355,1081.4 h13.78
  text ".Layer_Name" at 406,-1642.93 h23.62
Bottom Overlay:
  text "PMP21639PCB Rev D" at 3365,100 h80 r270
  text ".Layer_Name" at 406,-1642.93 h23.62
Top Paste:
  text ".Layer_Name" at 406,-1642.93 h23.62
Bottom Paste:
  text ".Layer_Name" at 406,-1642.93 h23.62
Top Solder:
  rectangle: 2625,1030 2770,1085
  rectangle: 2625,850 2770,905
  rectangle: 2625,402.48 2753.5,534.54
  rectangle: 2640,50 2768.78,108.1
  text ".Layer_Name" at 406,-1642.93 h23.62
  text ".Layer_Name" at 406,-1642.93 h23.62
Bottom Solder:
  rectangle: 2625,1030 2770,1085
  rectangle: 2625,850 2770,905
  rectangle: 2625,401.11 2753.44,534.51
  rectangle: 2640,50 2768.78,105
  text ".Layer_Name" at 406,-1642.93 h23.62
Drill Guide:
  text ".Layer_Name" at 406,-1642.93 h23.62
M1 Board Outline:
  lines w5: 2625,404.98 cw(c2625,415) 2614.98,415 2614.98,520 cw(c2625,520) 2625,530.02 2749.98,530 2749.98,845 2625,845 ; 2625,405 2749.98,405 2749.98,110 2600,110 2600,1125 ccw(c2585,1125) 2585,1140.02 2336.3,1140.02 ; 2625,844.98 cw(c2625,860) 2609.98,860 2609.98,895 cw(c2625,895) 2625,910.02 2749.98,910 2749.98,1025 2625,1025 ; 2625,1024.98 cw(c2625,1040) 2609.98,1040 2609.98,1075 cw(c2625,1075) 2625,1090.02 2749.98,1090 2749.98,1125 cw(c2765,1125) 2765,1140.02 ; 2336.19,1140.01 cw(c2336.3,1137.52) 2336.3,1140.02 ; 2336.19,1140.01 cw(c2336.3,1137.52) 2336.3,1140.02 ; 2336.19,1140.01 2335.69,1139.99 ccw(c2335,1130) 2324.98,1130 2324.98,900 2265.02,900 2265.02,1130 ccw(c2255,1130) 2255,1140.02 -85,1140.02 ccw(c-85,1125) -100.02,1125 -100,0 ccw(c-85,0) -85,-15.02 2585,-15.02 ccw(c2585,0) 2600.02,0 2600,45 2749.98,45 2749.98,0 ccw(c2765,0) 2765,-15.02 3552.48,-15.02 ccw(c3552.48,0) 3567.5,0 3567.5,1124.62 ccw(c3552.48,1124.62) 3552.48,1139.64 ; 2765,1140.02 ccw(c2765,1137.52) 2765,1140.02 ; 2765,1140.02 ccw(c2765,1137.52) 2765,1140.02 ; 2765,1140.02 3552.48,1139.64 ; 3552.48,1139.64 ccw(c3552.48,1124.62) 3552.48,1139.64 ; 3552.48,1139.64 3552.48,1139.64
  text ".Layer_Name" at 406,-1642.93 h23.62
M2 Board Dimensions:
  rectangle: -171,-1059.43 -46,-934.43
  rectangle: -46,-1184.43 329,-1059.43
  lines w7: -171,-1059.43 829,-1059.43 ; -46,-1184.43 -46,-934.43 ; 79,-1184.43 79,-934.43 ; 329,-1184.43 329,-934.43 ; 579,-1184.43 579,-934.43 ; -171,-1184.43 829,-1184.43 829,-934.43 -171,-934.43 -171,-1184.43
  lines w10: -180,44.98 -160,-15.02 ; -180,1080 -160,1140 ; -170,-15.02 -150,-15.02 ; -170,1140 -150,1140 ; -160,181.61 -160,-15.02 ; -160,943.37 -160,1140 ; -140,44.98 -160,-15.02 ; -140,1080 -160,1140 ; -100,-55 -100,-35 ; -40,-65 -100,-45 ; -40,-25 -100,-45 ; 969.09,-45 -100,-45 ; 1530.91,-45 2600,-45 ; 2540,-65 2600,-45 ; 2540,-25 2600,-45 ; 2600,-55 2600,-35 ; 2614.84,-55 2615.16,-75 ; 2674.68,-44.06 2615,-65 ; 2675.31,-84.05 2615,-65 ; 2730.41,-63.18 2615,-65 ; 3452.09,-51.82 3567.5,-50 ; 3507.19,-30.95 3567.5,-50 ; 3507.82,-70.94 3567.5,-50 ; 3567.34,-40 3567.66,-60
  text "1155.018 (mil)" at -124.01,191.61 h60 r90
  text "2700 (mil)" at 979.09,-80.99 h60
  text "952.619 (mil)" at 2740.97,-99.01 h60 r0.9
  text ".Layer_Name" at 406,-1642.93 h23.62
M3 3D STEP Top:
  text ".Layer_Name" at 406,-1642.93 h23.62
M4 3D STEP Bottom:
  text ".Layer_Name" at 406,-1642.93 h23.62
M5 Assembly Top:
  lines w10: -463,-1714.6 6137,-1714.6 ; -463,-1511.27 6139,-1511.27 ; -463,-1307.93 -463,-1917.93 3542,-1917.93 6139,-1917.93 6139,-1307.93 -462.5,-1307.93 -462.5,-1917.93 1113,-1917.93 ; 2002,-1917.93 2002,-1307.93 ; 3269,-1511.27 3269,-1307.93 ; 4109,-1511.27 4109,-1307.93 ; 4731,-1924.43 4731,-1721.6
  text "COMPONENTS MARKED 'DNP' SHOULD NOT BE POPULATED." at 982.5,-1102.93 h23.62
  text "ASSEMBLY VARIANT:" at 982,-1218.43 h23.62
  text ".VariantName" at 2018,-1218.43 h23.62
  text "PCB VIEWED FROM TOP SIDE" at -399.5,-1440.1 h23.62
  text "BOARD #:" at 2077,-1440.1 h23.62
  text ".PRJ_Number" at 2622.5,-1440.1 h23.62
  text "REV:" at 3467,-1440.1 h23.62
  text ".PCB_Rev" at 3758.5,-1440.1 h23.62
  text "SVN REV:" at 4305,-1440.1 h23.62
  text ".VersionControl_RevNumber" at 4811,-1440.1 h23.62
  text "TID #:" at 2077,-1643.43 h23.62
  text ".TID" at 2622.5,-1643.43 h23.62
  text "PLOT NAME =" at -399.5,-1848.77 h23.62
  text ".plot_File_Name" at 406,-1848.77 h23.62
  text "GENERATED    :" at 2079,-1848.77 h23.62
  text ".Print_Date" at 2948.5,-1848.77 h23.62
  text ".Print_Time" at 3677.5,-1848.77 h23.62
  text "TEXAS INSTRUMENTS" at 4942,-1848.77 h23.62
M6 Assembly Bottom:
  lines w10: -463.5,-1511.77 6138.5,-1511.77 ; -461.5,-1715.1 6138.5,-1715.1 ; 944.5,-1924.93 944.5,-1722.1 ; 1566.5,-1511.77 1566.5,-1308.43 ; 2406.5,-1511.77 2406.5,-1308.43 ; 3673.5,-1918.43 3673.5,-1308.43 ; 4562.5,-1918.43 6138,-1918.43 6138,-1308.43 -463.5,-1308.43 -463.5,-1918.43 2133.5,-1918.43 6138.5,-1918.43 6138.5,-1308.43
  text "COMPONENTS MARKED 'DNP' SHOULD NOT BE POPULATED." at 5931,-1102.43 h23.62
  text ".VariantName" at 4887,-1218.43 h23.62
  text "ASSEMBLY VARIANT:" at 5926,-1218.43 h23.62
  text ".VersionControl_RevNumber" at 864.5,-1440.6 h23.62
  text "SVN REV:" at 1370.5,-1440.6 h23.62
  text ".PCB_Rev" at 1917,-1440.6 h23.62
  text "REV:" at 2208.5,-1440.6 h23.62
  text ".PRJ_Number" at 3053,-1440.6 h23.62
  text "BOARD #:" at 3598.5,-1440.6 h23.62
  text "PCB VIEWED FROM BOTTOM SIDE" at 6075,-1440.6 h23.62
  text ".TID" at 3053,-1643.93 h23.62
  text "TID #:" at 3598.5,-1643.93 h23.62
  text "TEXAS INSTRUMENTS" at 733.5,-1849.27 h23.62
  text ".Print_Time" at 1998,-1849.27 h23.62
  text ".Print_Date" at 2727,-1849.27 h23.62
  text "GENERATED    :" at 3596.5,-1849.27 h23.62
  text ".plot_File_Name" at 5269.5,-1849.27 h23.62
  text "PLOT NAME =" at 6075,-1849.27 h23.62
M9 Title Sheet:
  drawing of 57 lines, arcs and shapes, not listed
  text "1" at 568.84,7252.07 h23.62
  text "2" at 3064.5,7252.07 h23.62
  text "3" at 5553.84,7252.07 h23.62
  text "4" at 8060.51,7252.07 h23.62
  text "5" at 10559.5,7252.07 h23.62
  text "6" at 13064.5,7252.07 h23.62
  text "A" at -587.5,6109.07 h23.62
  text "A" at 14212.5,6109.07 h23.62
  text "B" at -587.5,3729.07 h23.62
  text "B" at 14212.5,3729.07 h23.62
  text "C" at -587.5,1354.07 h23.62
  text "C" at 14212.5,1354.07 h23.62
  text "PROJECT TITLE:" at 11172.5,-506.93 h23.62
  text ".PRJ_Title" at 11222.5,-640.26 h23.62
  text "DESIGNED FOR:" at 11172.5,-807.93 h23.62
  text ".PRJ_Customer" at 11222.5,-947.93 h23.62
  text "D" at -587.5,-1015.93 h23.62
  text "D" at 14212.5,-1015.93 h23.62
  text "FILE NAME:" at 11172.5,-1107.93 h23.62
  text ".PCB_File_Name_No_Path" at 11222.5,-1227.93 h23.62
  text "Texas Instruments (TI) and/or its licensors do not warrant the accuracy or completeness of this specification" at 6203,-1389.77 h23.62
  text "ENGINEER:" at 11172.5,-1397.93 h23.62
  text "LAYOUT BY:" at 12677.5,-1397.93 h23.62
  text "or any information contained therein. TI and/or its licensors do not warrant that this design will meet" at 6158.01,-1502.44 h23.62
  text ".PRJ_Engineer" at 11222.5,-1552.92 h23.62
  text ".PCB_Layout" at 12728,-1552.92 h23.62
  text "the specifications, will be suitable for your application or fit for any particular purpose, or will operate in" at 6158.01,-1615.1 h23.62
  text ".Layer_Name" at 406,-1642.93 h23.62
  text "ALTIUM DESIGNER VERSION:" at 12677.5,-1707.93 h23.62
  text "an implementation. TI and/or its licensors do not warrant that the design is production worthy. You should" at 6158.01,-1727.77 h23.62
  text "completely validate and test your design implementation to confirm the system functionality for your application." at 6203,-1840.43 h23.62
  text ".print_Scale" at 11222.5,-1841.26 h23.62
  text ".Application_BuildNumber" at 12728,-1841.26 h23.62
  text "1" at 568.84,-2047.93 h23.62
  text "2" at 3064.5,-2047.93 h23.62
  text "3" at 5553.84,-2047.93 h23.62
  text "4" at 8060.51,-2047.93 h23.62
  text "5" at 10559.5,-2047.93 h23.62
  text "6" at 13064.5,-2047.93 h23.62
M10 Fab Notes:
  drawing of 173 lines, arcs and shapes, not listed
  text "DESIGN INFORMATION" at 12207.02,5416.57 h60
  text "MIN. TRACK WIDTH:" at 11562.46,5236.57 h60
  text "8" at 12658.7,5236.57 h60
  text "MIL" at 12813.46,5236.57 h60
  text "MIN. CLEARANCE:" at 11562.46,5104.57 h60
  text "0.2" at 12598.7,5104.57 h60
  text "mm" at 12813.46,5104.57 h60
  text "MIN. VIA PAD SIZE:" at 11562.46,4972.57 h60
  text "24" at 12628.71,4972.57 h60
  text "MIL" at 12813.46,4972.57 h60
  text "0.05mm (2MIL)" at 12257.46,4830.86 h60
  text "MINIMUM ANNULAR RING" at 11233.23,4826.57 h60
  text "EXTERNAL" at 12965.46,4826.57 h60
  text "PER" at 11433.23,4708.57 h60
  text "IPC-D-275 CLASS 2 LEVEL C" at 11653.23,4708.57 h60
  text "MIL, HOLES" at 13141.46,4596.28 h60
  text "+/-" at 12749,4595.57 h60
  text "+/-" at 13603,4595.57 h60
  text "REGISTRATION TOLERANCES:" at 11233.23,4590.57 h60
  text "METAL" at 12433,4590.57 h60
  text "5" at 13009.2,4590.57 h60
  text "3" at 13842.2,4590.57 h60
  text "MIL" at 13958.46,4590.57 h60
  text "+/-" at 13603,4477.57 h60
  text "HOLE SIZE TOLERANCE (UNLESS OTHERWISE SPECIFIED):" at 11233.23,4472.57 h60
  text "3" at 13842.2,4472.57 h60
  text "MIL" at 13958.46,4472.57 h60
  text "MATERIAL:" at 11158.46,4263.11 h60
  text "FR-4 High Tg" at 12144.9,4122.78 h60
  text "FR-408" at 11579.46,4114.21 h60
  text "OTHER" at 13067.46,4114.21 h60
  text "X" at 11990,4110.57 h60
  text "62 MIL (1.6mm) +/-10%" at 11899.56,3951.49 h60
  text "THICKNESS:" at 11233.23,3947.21 h60
  text "X" at 11771.4,3947.21 h60
  text "OTHER" at 13184.46,3947.21 h60
  text "TOLERANCE:" at 11233.23,3789.21 h60
  text "X" at 12072.53,3789.21 h60
  text "ANSI IPC-6012 TYPE 3 CLASS 2" at 12259.48,3789.21 h60
  text "OTHER +/-" at 12259.46,3633.21 h60
  text "BOW & TWIST:" at 11233.23,3476.21 h60
  text "X" at 12072.53,3476.21 h60
  text "ANSI IPC-6012 TYPE 3 CLASS 2" at 12259.48,3476.21 h60
  text "OTHER +/-" at 12259.46,3317.7 h60
  text "DRILLING:" at 11158.46,3179.21 h60
  text "REFERENCE:" at 11233.23,3062.21 h60
  text "X" at 11881.46,3062.21 h60
  text "AS SHOWN" at 12068.46,3062.21 h60
  text "X" at 12782.46,3062.21 h60
  text "NC_DRILL FILES" at 12919.46,3062.21 h60
  text "PTH COPPER THICKNESS:" at 11233.23,2904.21 h60
  text "X" at 12363.46,2904.21 h60
  text "20-30 um" at 12500.46,2904.21 h60
  text "OTHER" at 13217.46,2904.21 h60
  text "BOARD FINISH:" at 11158.46,2745.21 h60
  text "SILKSCREEN:" at 11313.68,2627.21 h60
  text "X" at 12262.46,2627.21 h60
  text "TOP" at 12388.46,2627.21 h60
  text "X" at 12772.46,2627.21 h60
  text "BOTTOM" at 12899.46,2627.21 h60
  text "SILKSCREEN COLOR:" at 11313.68,2460.21 h60
  text "X" at 12261.42,2460.21 h60
  text "WHITE" at 12388.46,2460.21 h60
  text "OTHER" at 12899.46,2460.21 h60
  text "X" at 12392.42,2301.01 h60
  text "GREEN" at 12519.46,2301.01 h60
  text "OTHER" at 13137.46,2301.01 h60
  text "SOLDER RESIST COLOR:" at 11313.68,2290.21 h60
  text "X" at 12392.42,2131.01 h60
  text "MATTE" at 12519.46,2131.01 h60
  text "SEMI-GLOSS" at 13137,2130.37 h60
  text "IMMERSION GOLD (ENIG)" at 12219.46,1942.49 h60
  text "ENEPIG" at 13557,1939.21 h60
  text "SURFACE FINISH:" at 11158.46,1938.21 h60
  text "X" at 12032.51,1938.21 h60
  text "IMM. TIN/SILVER OR EQUIV" at 11488,1781.21 h60
  text "OTHER" at 12919.46,1781.21 h60
  text "ARRAY/PANEL:" at 11158.46,1602.21 h60
  text "CUT AND TRIM PER M1 BOARD OUTLINE" at 12219.46,1597.92 h60
  text "N.C. ROUTE" at 12219.46,1446.21 h60
  text "X" at 12898.46,1446.21 h60
  text "V. SCORE" at 13085.46,1446.21 h60
  text "CERTIFICATION:" at 11158.46,1309.21 h60
  text "MATERIALS AND WORKMANSHIP FOR ALL PCBS" at 11883.46,1309.21 h60
  text "TO MEET OR EXCEED THE REQUIREMENTS OF:" at 11883.46,1211.21 h60
  text "X" at 11509.96,1074.7 h60
  text "ANSI IPC-A-600F CLASS ->" at 11648.96,1074.7 h60
  text "X" at 13288.02,1074.7 h60
  text "2" at 13406.96,1074.7 h60
  text "1" at 13091.96,1073.21 h60
  text "3" at 13760.96,1073.21 h60
  text "X" at 12324.02,915.21 h60
  text "RoHS" at 12460.96,915.21 h60
  text "OTHER" at 13105.36,915.21 h60
  text "PER ORDER" at 13502.42,915.21 h60
  text "ALL BOARDS MUST MEET OR EXCEED UL94-V0 REQUIREMENTS." at 11186,749.57 h60
  text "PCB MUST BEAR THE UL94V-0 UL REGISTERED MATERIAL ID NUMBER" at 11186,629.57 h60
  text "ADDITIONAL REQUIREMENTS:" at 11158.46,456.21 h60
  text "MICROSECTION:" at 11233.23,341.21 h60
  text "YES" at 12138.96,341.21 h60
  text "REQUIRED" at 13000.46,185.06 h60
  text "BARE BOARD ELEC. TEST:" at 11233.23,182.21 h60
  text "NONE" at 12538.96,182.21 h60
  text "X" at 12873.46,182.21 h60
  text "PER ORDER" at 13592.46,182.21 h60
  text ".Layer_Name" at 406,-1642.93 h60
M11 Gerber Information:
  lines w10: -463,-1714.6 6137,-1714.6 ; -463,-1511.27 6139,-1511.27 ; -463,-1307.93 -463,-1917.93 3542,-1917.93 6139,-1917.93 6139,-1307.93 -462.5,-1307.93 -462.5,-1917.93 1113,-1917.93 ; 2002,-1917.93 2002,-1307.93 ; 3269,-1511.27 3269,-1307.93 ; 4109,-1511.27 4109,-1307.93 ; 4731,-1924.43 4731,-1721.6
  text "ALL ARTWORK VIEWED FROM TOP SIDE" at -399.5,-1440.1 h23.62
  text "BOARD #:" at 2077,-1440.1 h23.62
  text ".PRJ_Number" at 2622.5,-1440.1 h23.62
  text "REV:" at 3467,-1440.1 h23.62
  text ".PCB_Rev" at 3758.5,-1440.1 h23.62
  text "SVN REV:" at 4305,-1440.1 h23.62
  text ".VersionControl_RevNumber" at 4811,-1440.1 h23.62
  text "LAYER NAME =" at -399.5,-1642.93 h23.62
  text "TID #:" at 2077,-1643.43 h23.62
  text ".TID" at 2622.5,-1643.43 h23.62
  text "PLOT NAME =" at -399.5,-1848.77 h23.62
  text ".plot_File_Name" at 406,-1848.77 h23.62
  text "GENERATED    :" at 2079,-1848.77 h23.62
  text ".Print_Date" at 2948.5,-1848.77 h23.62
  text ".Print_Time" at 3677.5,-1848.77 h23.62
  text "TEXAS INSTRUMENTS" at 4942,-1848.77 h23.62
M12 Stackup:
  drawing of 295 lines, arcs and shapes, not listed
  text "Layer" at 9610.35,7020 h60
  text "Name" at 10020.26,7020 h60
  text "Material" at 10960,7020 h60
  text "Thickness" at 11819.77,7020 h60
  text "Constant" at 12469.6,7020 h60
  text "Board Layer Stack" at 13039.46,7020 h60
  text "1" at 9610.35,6900 h60
  text "Top Overlay" at 10020.26,6900 h60
  text "2" at 9610.35,6780 h60
  text "Top Solder" at 10020.26,6780 h60
  text "Solder Resist" at 10960,6780 h60
  text "0.40mil" at 11819.77,6780 h60
  text "3.5" at 12469.6,6780 h60
  text "3" at 9610.35,6660 h60
  text "Top Layer" at 10020.26,6660 h60
  text "Copper" at 10960,6660 h60
  text "2.76mil" at 11819.77,6660 h60
  text "4" at 9610.35,6540 h60
  text "Dielectric 2" at 10020.26,6540 h60
  text "10.00mil" at 11819.77,6540 h60
  text "4.2" at 12469.6,6540 h60
  text "5" at 9610.35,6420 h60
  text "Signal Layer 1" at 10020.26,6420 h60
  text "Copper" at 10960,6420 h60
  text "2.76mil" at 11819.77,6420 h60
  text "6" at 9610.35,6300 h60
  text "Dielectric 3" at 10020.26,6300 h60
  text "10.00mil" at 11819.77,6300 h60
  text "4.2" at 12469.6,6300 h60
  text "7" at 9610.35,6180 h60
  text "Signal Layer 2" at 10020.26,6180 h60
  text "Copper" at 10960,6180 h60
  text "2.76mil" at 11819.77,6180 h60
  text "8" at 9610.35,6060 h60
  text "Dielectric1" at 10020.26,6060 h60
  text "FR-4" at 10960,6060 h60
  text "59.20mil" at 11819.77,6060 h60
  text "4.8" at 12469.6,6060 h60
  text "9" at 9610.35,5940 h60
  text "Bottom Layer" at 10020.26,5940 h60
  text "Copper" at 10960,5940 h60
  text "2.76mil" at 11819.77,5940 h60
  text "10" at 9610.35,5820 h60
  text "Bottom Solder" at 10020.26,5820 h60
  text "Solder Resist" at 10960,5820 h60
  text "0.40mil" at 11819.77,5820 h60
  text "3.5" at 12469.6,5820 h60
  text "11" at 9610.35,5700 h60
  text "Bottom Overlay" at 10020.26,5700 h60
  text ".Layer_Name" at 406,-1642.93 h23.62
M13 Component Bodies Top:
  text ".Layer_Name" at 406,-1642.93 h23.62
M14 Component Bodies Bottom:
  text ".Layer_Name" at 406,-1642.93 h23.62
M15 Courtyards Top:
  text ".Layer_Name" at 406,-1642.93 h23.62
M16 Courtyards Bottom:
  text ".Layer_Name" at 406,-1642.93 h23.62
Drill Drawing:
  drawing of 168 lines, arcs and shapes, not listed
  text "Symbol" at 5189.59,2828.98 h72
  text "Quantity" at 5490.16,2828.98 h72
  text "Finished Hole Size" at 5822.16,2828.98 h72
  text "Plated" at 6458.72,2828.98 h72
  text "Hole Type" at 6717.86,2828.98 h72
  text "Drill Layer Pair" at 7093.02,2828.98 h72
  text "Hole Tolerance" at 7817.35,2828.98 h72
  text "1" at 5490.16,2704.66 h60
  text "33.00mil (0.838mm)" at 5822.16,2704.66 h60
  text "NPTH" at 6458.72,2704.66 h60
  text "Round" at 6717.86,2704.66 h60
  text "Top Layer - Bottom Layer" at 7093.02,2704.66 h60
  text "22" at 5490.16,2580.34 h60
  text "7.87mil (0.200mm)" at 5822.16,2580.34 h60
  text "PTH" at 6458.72,2580.34 h60
  text "Round" at 6717.86,2580.34 h60
  text "Top Layer - Bottom Layer" at 7093.02,2580.34 h60
  text "74" at 5490.16,2456.02 h60
  text "11.81mil (0.300mm)" at 5822.16,2456.02 h60
  text "PTH" at 6458.72,2456.02 h60
  text "Round" at 6717.86,2456.02 h60
  text "Top Layer - Bottom Layer" at 7093.02,2456.02 h60
  text "14" at 5490.16,2331.7 h60
  text "15.75mil (0.400mm)" at 5822.16,2331.7 h60
  text "PTH" at 6458.72,2331.7 h60
  text "Round" at 6717.86,2331.7 h60
  text "Top Layer - Bottom Layer" at 7093.02,2331.7 h60
  text "6" at 5490.16,2207.38 h60
  text "18.00mil (0.457mm)" at 5822.16,2207.38 h60
  text "PTH" at 6458.72,2207.38 h60
  text "Round" at 6717.86,2207.38 h60
  text "Top Layer - Bottom Layer" at 7093.02,2207.38 h60
  text "2" at 5490.16,2083.06 h60
  text "25.59mil (0.650mm)" at 5822.16,2083.06 h60
  text "PTH" at 6458.72,2083.06 h60
  text "Round" at 6717.86,2083.06 h60
  text "Top Layer - Bottom Layer" at 7093.02,2083.06 h60
  text "5" at 5490.16,1958.74 h60
  text "27.56mil (0.700mm)" at 5822.16,1958.74 h60
  text "PTH" at 6458.72,1958.74 h60
  text "Round" at 6717.86,1958.74 h60
  text "Top Layer - Bottom Layer" at 7093.02,1958.74 h60
  text "A" at 5164.31,1948.75 h55.25
  text "2" at 5490.16,1834.42 h60
  text "28.00mil (0.711mm)" at 5822.16,1834.42 h60
  text "PTH" at 6458.72,1834.42 h60
  text "Round" at 6717.86,1834.42 h60
  text "Top Layer - Bottom Layer" at 7093.02,1834.42 h60
  text "B" at 5164.31,1824.43 h55.25
  text "4" at 5490.16,1710.1 h60
  text "32.00mil (0.813mm)" at 5822.16,1710.1 h60
  text "PTH" at 6458.72,1710.1 h60
  text "Round" at 6717.86,1710.1 h60
  text "Top Layer - Bottom Layer" at 7093.02,1710.1 h60
  text "6" at 5490.16,1585.78 h60
  text "33.47mil (0.850mm)" at 5822.16,1585.78 h60
  text "PTH" at 6458.72,1585.78 h60
  text "Round" at 6717.86,1585.78 h60
  text "Top Layer - Bottom Layer" at 7093.02,1585.78 h60
  text "2" at 5490.16,1461.46 h60
  text "39.37mil (1.000mm)" at 5822.16,1461.46 h60
  text "PTH" at 6458.72,1461.46 h60
  text "Round" at 6717.86,1461.46 h60
  text "Top Layer - Bottom Layer" at 7093.02,1461.46 h60
  text "2" at 5490.16,1337.14 h60
  text "40.00mil (1.016mm)" at 5822.16,1337.14 h60
  text "PTH" at 6458.72,1337.14 h60
  text "Round" at 6717.86,1337.14 h60
  text "Top Layer - Bottom Layer" at 7093.02,1337.14 h60
  text "D" at 5164.31,1327.15 h55.25
  text "4" at 5490.16,1212.82 h60
  text "41.34mil (1.050mm)" at 5822.16,1212.82 h60
  text "PTH" at 6458.72,1212.82 h60
  text "Round" at 6717.86,1212.82 h60
  text "Top Layer - Bottom Layer" at 7093.02,1212.82 h60
  text "8" at 5490.16,1088.5 h60
  text "42.13mil (1.070mm)" at 5822.16,1088.5 h60
  text "PTH" at 6458.72,1088.5 h60
  text "Round" at 6717.86,1088.5 h60
  text "Top Layer - Bottom Layer" at 7093.02,1088.5 h60
  text "F" at 5164.31,1078.51 h55.25
  text "2" at 5490.16,964.18 h60
  text "49.21mil (1.250mm)" at 5822.16,964.18 h60
  text "PTH" at 6458.72,964.18 h60
  text "Round" at 6717.86,964.18 h60
  text "Top Layer - Bottom Layer" at 7093.02,964.18 h60
  text "3" at 5490.16,839.86 h60
  text "63.00mil (1.600mm)" at 5822.16,839.86 h60
  text "PTH" at 6458.72,839.86 h60
  text "Round" at 6717.86,839.86 h60
  text "Top Layer - Bottom Layer" at 7093.02,839.86 h60
  text "C" at 5164.31,829.87 h55.25
  text "4" at 5490.16,715.54 h60
  text "23.62mil (0.600mm)" at 5822.16,715.54 h60
  text "PTH" at 6458.72,715.54 h60
  text "Slot" at 6717.86,715.54 h60
  text "Top Layer - Bottom Layer" at 7093.02,715.54 h60
  text "1" at 5490.16,591.22 h60
  text "40.00mil (1.016mm)" at 5822.16,591.22 h60
  text "PTH" at 6458.72,591.22 h60
  text "Slot" at 6717.86,591.22 h60
  text "Top Layer - Bottom Layer" at 7093.02,591.22 h60
  text "3" at 5490.16,466.9 h60
  text "80.00mil (2.032mm)" at 5822.16,466.9 h60
  text "PTH" at 6458.72,466.9 h60
  text "Slot" at 6717.86,466.9 h60
  text "Top Layer - Bottom Layer" at 7093.02,466.9 h60
  text "E" at 5164.31,456.91 h55.25
  text "1" at 5490.16,342.58 h60
  text "80.00mil (2.032mm)" at 5822.16,342.58 h60
  text "PTH" at 6458.72,342.58 h60
  text "Slot" at 6717.86,342.58 h60
  text "Top Layer - Bottom Layer" at 7093.02,342.58 h60
  text "166 Total" at 5490.16,218.26 h60
  text "Slot definitions :" at 5189.59,131.24 h60
  text "Routed Path Length" at 5640.31,131.24 h60
  text "= Calculated from tool start centre position to tool end centre position." at 6180.05,131.24 h60
  text "Hole Length" at 5640.31,81.51 h60
  text "= Routed Path Length + Tool Size = Slot length as defined in the PCB layout" at 5980.24,81.51 h60
  text ".Layer_Name" at 406,-1642.93 h23.62
M17 Embedded Cavity:
  text ".Layer_Name" at 406,-1642.93 h23.62
M18 Embedded Assembly:
  text ".Layer_Name" at 406,-1642.93 h23.62
M19 Embedded Keepout:
  text ".Layer_Name" at 406,-1642.93 h23.62

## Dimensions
-171,-1184.43 to 829,-1184.43 on M2 Board Dimensions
